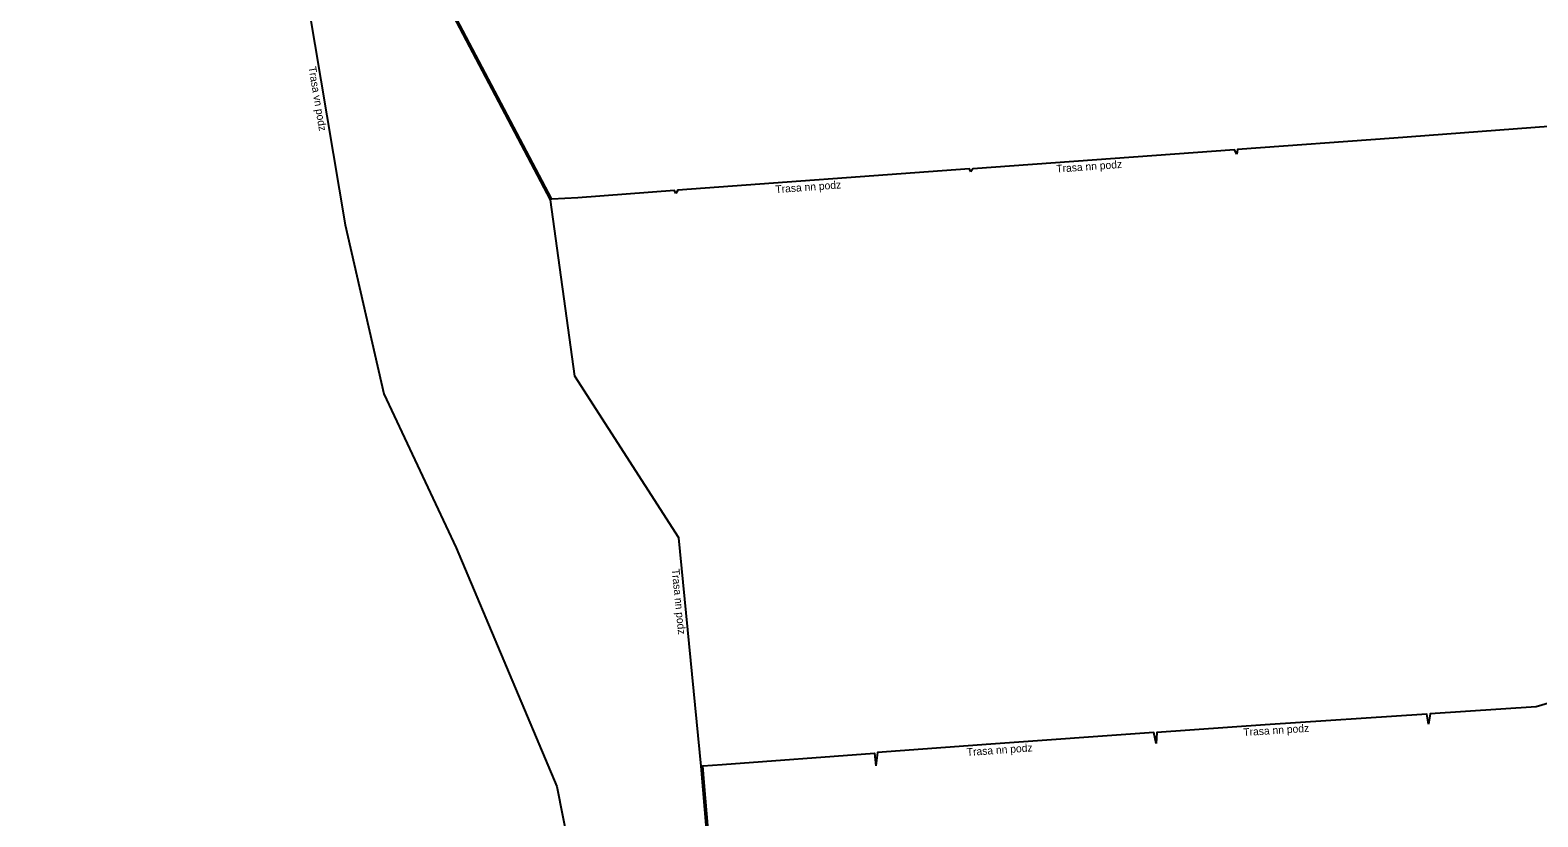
# Model space of a CAD drawing. Extents: x -873583 to -872966, y -1012951 to -1012536.
# Drawn here: x -873492.1 to -873394.3, y -1012723 to -1012672 of the extents above; entities that cross this region are included whole.
import ezdxf

# ---------------------------------------------------------------- set-up
doc = ezdxf.new("R2010")
doc.units = 0
for name, color, linetype in [('Popiskový text - Ostatní atributy Trasy', 7, 'Continuous'), ('Spojnice NN', 7, 'Continuous'), ('Spojnice VN', 7, 'Continuous')]:
    doc.layers.add(name, color=color, linetype=linetype)

msp = doc.modelspace()

# ---------------------------------------------------------------- linework, layer by layer
at = {"layer": 'Spojnice NN'}
for points in [[(-873427.858, -1012770.594), (-873428.264, -1012770.636), (-873429.387, -1012771.841), (-873429.992, -1012768.414), (-873430.021, -1012768.346), (-873447.579, -1012731.499), (-873448.573, -1012719.725), (-873450.034, -1012704.924), (-873456.773, -1012694.431), (-873458.348, -1012682.983), (-873469.466, -1012661.885), (-873469.688, -1012658.782), (-873470.42, -1012648.115), (-873469.405, -1012648.017), (-873469.246, -1012647.953)], [(-873450.212, -1012682.577), (-873450.315, -1012682.387), (-873456.573, -1012682.848), (-873458.26, -1012682.936), (-873469.369, -1012661.857), (-873470.314, -1012648.209), (-873469.399, -1012648.165), (-873469.246, -1012647.953)], [(-873344.133, -1012674.804), (-873344.267, -1012674.5), (-873350.667, -1012674.977), (-873403.665, -1012678.977), (-873413.794, -1012679.713), (-873413.855, -1012680.027)], [(-873413.855, -1012680.027), (-873414.006, -1012679.734), (-873430.974, -1012680.968), (-873431.089, -1012681.171)], [(-873431.089, -1012681.171), (-873431.189, -1012680.985), (-873450.098, -1012682.37), (-873450.212, -1012682.577)], [(-873359.33, -1012708.645), (-873359.456, -1012707.896), (-873369.806, -1012708.595), (-873394.427, -1012715.878), (-873401.315, -1012716.333), (-873401.424, -1012717.008)], [(-873401.424, -1012717.008), (-873401.531, -1012716.352), (-873411.998, -1012717.042), (-873419.03, -1012717.549), (-873419.076, -1012718.271)], [(-873419.076, -1012718.271), (-873419.222, -1012717.556), (-873429.79, -1012718.313), (-873437.141, -1012718.856), (-873437.249, -1012719.707)], [(-873402.088, -1012758.288), (-873402.065, -1012758.06), (-873402.398, -1012757.174), (-873429.93, -1012768.303), (-873447.48, -1012731.473), (-873448.383, -1012720.789), (-873448.473, -1012719.717), (-873447.223, -1012719.617), (-873437.339, -1012718.881), (-873437.249, -1012719.707)]]:
    msp.add_lwpolyline(points, dxfattribs=at)
at = {"layer": 'Spojnice VN'}
msp.add_lwpolyline([(-873491.98, -1012598.14), (-873491.83, -1012599.85), (-873492.088, -1012603.505), (-873490.976, -1012613.282), (-873477.585, -1012611.672), (-873477.233, -1012616.523), (-873476.512, -1012619.584), (-873475.862, -1012635.453), (-873477.152, -1012636.637), (-873476.923, -1012647.799), (-873475.982, -1012658.878), (-873471.673, -1012684.612), (-873469.161, -1012695.58), (-873464.459, -1012705.574), (-873457.942, -1012721.062), (-873455.68, -1012732.426), (-873437.429, -1012765.017)], dxfattribs=at)

# ---------------------------------------------------------------- texts
at = {"layer": 'Popiskový text - Ostatní atributy Trasy'}
for s, rotation, p in [('Trasa vn podz', 279.50555, (-873474.046, -1012674.374)), ('Trasa nn podz', 4.16216, (-873425.534, -1012681.225)), ('Trasa nn podz', 4.18901, (-873443.748, -1012682.556)), ('Trasa nn podz', 275.63862, (-873450.487, -1012706.953)), ('Trasa nn podz', 3.77011, (-873413.409, -1012717.786)), ('Trasa nn podz', 4.10276, (-873431.339, -1012719.077))]:
    msp.add_text(s, height=0.5, rotation=rotation, dxfattribs=at).set_placement(p)

doc.saveas('drawing.dxf')
